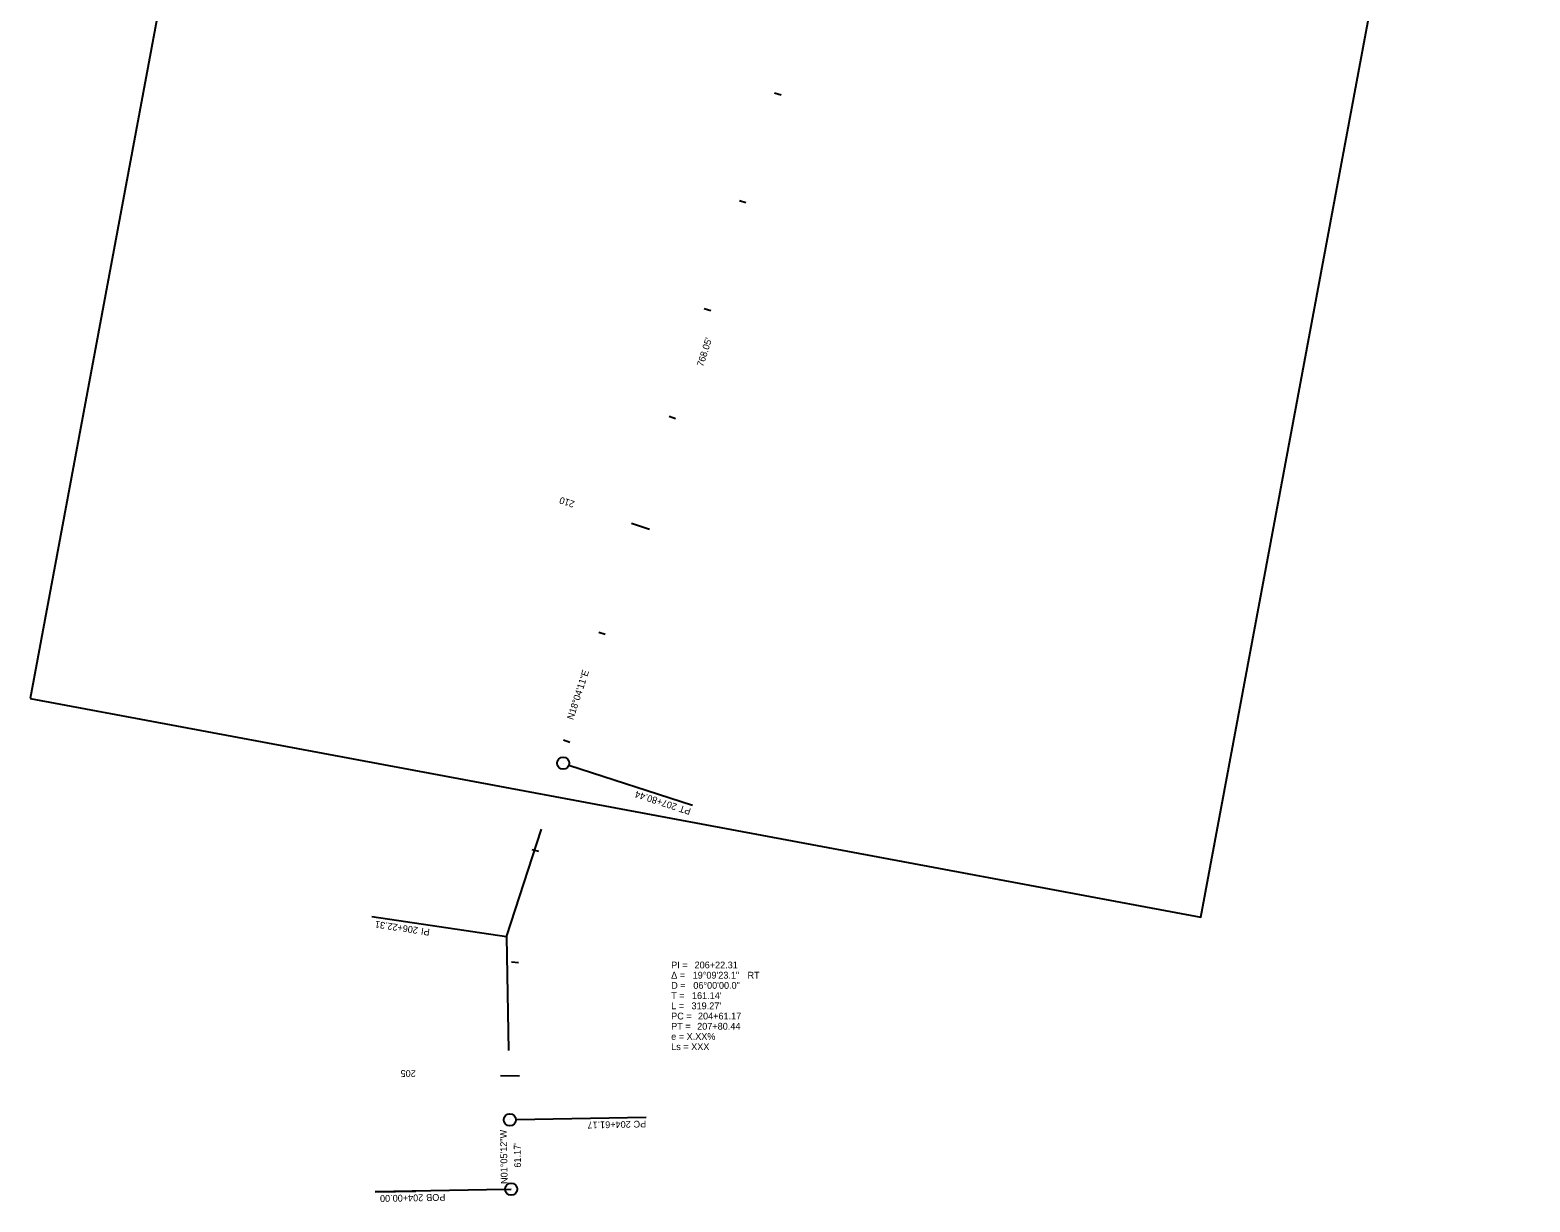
# Model space of a CAD drawing. Extents: x 1802364 to 1804577, y 572742 to 575010.
# Drawn here: x 1802779 to 1804101, y 572742 to 573774 of the extents above; entities that cross this region are included whole.
import ezdxf

# ---------------------------------------------------------------- set-up
doc = ezdxf.new("R2010")
doc.units = 0
for name, color, linetype in [('_CIVIL_CONSTRUCTION', 7, 'Continuous'), ('MOD_COR_TemplateDrop', 7, 'Continuous'), ('MOD_Points', 7, 'Continuous')]:
    doc.layers.add(name, color=color, linetype=linetype)

msp = doc.modelspace()

# ---------------------------------------------------------------- linework, layer by layer
at = {"layer": '_CIVIL_CONSTRUCTION'}
for p, q in [((1803435.4, 573719.1), (1803441.1, 573717.3)), ((1803404.4, 573624.1), (1803410.1, 573622.2)), ((1803373.4, 573529), (1803379.1, 573527.1)), ((1803342.4, 573433.9), (1803348.1, 573432.1)), ((1803309.1, 573339.6), (1803325, 573334.4)), ((1803280.3, 573243.8), (1803286, 573241.9)), ((1803249.3, 573148.7), (1803255, 573146.9)), ((1803249, 573128.3), (1803249, 573128.3)), ((1803254, 573126.6), (1803363, 573091.1)), ((1803363, 573091.1), (1803363, 573091.1)), ((1803199, 572975.1), (1803230, 573070.2)), ((1803221.4, 573052.2), (1803227.3, 573050.8)), ((1803199, 572975.1), (1803080.3, 572992.8)), ((1803080.3, 572992.8), (1803080.3, 572992.8)), ((1803199, 572975.1), (1803200.9, 572875.1)), ((1803203.5, 572953.2), (1803209.5, 572952.5)), ((1803193.7, 572853), (1803210.5, 572852.6)), ((1803202, 572814), (1803202, 572814)), ((1803207.4, 572814.1), (1803322, 572816.3)), ((1803322, 572816.3), (1803322, 572816.3)), ((1803197.9, 572752.7), (1803083.2, 572750.5)), ((1803083.2, 572750.5), (1803119.2, 572751.2)), ((1803197.2, 572752.7), (1803203.2, 572752.8)), ((1803203.2, 572752.8), (1803203.2, 572752.8))]:
    msp.add_line(p, q, dxfattribs=at)
for centre in [(1803249, 573128.3), (1803202, 572814), (1803203.2, 572752.8)]:
    msp.add_circle(centre, 5.34, dxfattribs=at)
at = {"layer": 'MOD_COR_TemplateDrop'}
msp.add_lwpolyline([(1802779, 573185.2), (1803811.2, 572992.6), (1804101.3, 574547.6), (1803069.1, 574740.2)], close=True, dxfattribs=at)

# ---------------------------------------------------------------- texts
at = {"layer": '_CIVIL_CONSTRUCTION'}
for s, rotation, p in [('210', 161.9303, (1803259.6, 573358.9)), ('N18°04\'11"E', 71.9303, (1803257.8, 573166)), ('207+80.44', 161.9303, (1803349.8, 573092.2)), ('PT', 161.9303, (1803362.1, 573088.2)), ('206+22.31', 171.5085, (1803121.3, 572983.7)), ('PI ', 171.5085, (1803131.7, 572982.1)), ('205', 178.757, (1803119.1, 572857.6)), ('204+61.17', 181.0867, (1803308.5, 572813)), ('PC', 181.0867, (1803322.1, 572813.3)), ('N01°05\'12"W', 91.0867, (1803200.1, 572757.5)), ('204+00.00', 181.0867, (1803125.6, 572748.3)), ('POB ', 181.0867, (1803145.1, 572748.7))]:
    msp.add_text(s, height=6, rotation=rotation, dxfattribs=at).set_placement(p)
for s, p in [('Δ = ', (1803344.2, 572938.4)), ('PI = ', (1803344.2, 572947.4)), ('19°09\'23.1"', (1803363.1, 572938.4)), ('206+22.31', (1803364.8, 572947.4)), (' RT', (1803409.3, 572938.4)), ('D = ', (1803344.2, 572929.4)), ('06°00\'00.0"', (1803363.7, 572929.4)), ('T = ', (1803344.2, 572920.4)), ('L = ', (1803344.2, 572911.4)), ("319.27'", (1803362.1, 572911.4)), ("161.14'", (1803362.5, 572920.4)), ('PC = ', (1803344.2, 572902.4)), ('204+61.17', (1803367.8, 572902.4)), ('e = X.XX%', (1803344.2, 572884.4)), ('PT = ', (1803344.2, 572893.4)), ('207+80.44', (1803367.1, 572893.4)), ('Ls = XXX', (1803344.2, 572875.4))]:
    msp.add_text(s, height=6, dxfattribs=at).set_placement(p)
at = {"layer": 'MOD_Points'}
for s, rotation, p in [("768.05'", 71.9303, (1803372.3, 573477.2)), ("61.17'", 91.0867, (1803211.8, 572771.9))]:
    msp.add_text(s, height=6, rotation=rotation, dxfattribs=at).set_placement(p)

doc.saveas('drawing.dxf')
